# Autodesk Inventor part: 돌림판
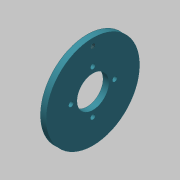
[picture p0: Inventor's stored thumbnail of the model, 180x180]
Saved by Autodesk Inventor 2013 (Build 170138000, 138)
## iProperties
Created: 2019-10
Part Number: 돌림판
Material: 스테인리스강
Document SubType Name: Modeling
Designer: mduedu
Density: 1 g/cm^3
Author: mduedu
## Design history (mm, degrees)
sketch "스케치1" dims "d3" = 30
  geometry: C1 r 32 at (0, 0); C2 r 11 at (0, 0); C3 r 1.7 at (15, 0); C4 r 1.7 at (0, 15); C5 r 1.7 at (-15, 0); C6 r 1.7 at (0, -15); 2 further points
  constraints: 6 centre point, 3 coincident, 2 horizontal alignment, 11 other
  dimensions: "d0" = 64 diameter of C1; "d2" = 3.4 diameter of C3; "d4" = 22 diameter of C2; "d7" = 360 deg dimension on point (0, 0) C3.centre (derived)
extrude "돌출1" new body sketch "스케치1" distance "d9" = 4; taper "d10" = 0 deg
sketch "스케치2" dims "d11" = 54
  geometry: 3 further points
  constraints: 2 vertical alignment, 1 coincident, 2 other
hole "구멍1" sketch "스케치2" at (0, 27) diameter "d13" = 3.242; stored, may be unused: countersink angle "d17" = 90 deg, drill point angle "d19" = 118 deg; dims "d14" = 6, "d15" = 4, "d16" = 2, "d18" = 8
node "솔리드1"
